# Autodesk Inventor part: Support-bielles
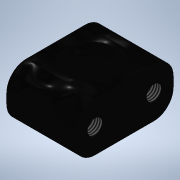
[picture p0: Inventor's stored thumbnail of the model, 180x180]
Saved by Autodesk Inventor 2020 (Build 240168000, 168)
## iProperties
Created: 2023-10
Part Number: Support-bielles
Material: Générique
Document SubType Name: Modeling
Designer: bruno
Density: 1 g/cm^3
Appearance: Noir
Author: bruno
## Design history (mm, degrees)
sketch "Esquisse1"
  geometry: L1 (4, 0)-(6, 0); L2 (10, -4)-(10, -16); L3 (6, -20)-(4, -20); L4 (0, -16)-(0, -4); A1 r 4 centre (6, -4) between (10, -4) and (6, 0); A2 r 4 centre (4, -4) between (4, 0) and (0, -4); A3 r 4 centre (4, -16) between (0, -16) and (4, -20); A4 r 4 centre (6, -16) between (6, -20) and (10, -16); 4 further points
  constraints: 8 end point, 8 point on circle, 8 point on line, 8 tangent, 4 centre point, 3 equal radius, 2 parallel, 1 horizontal, 1 perpendicular
  dimensions: "d0" = 10 distance of point (10, -20) point (0, -20); "d1" = 20 distance of point (10, 0) point (10, -20); "d2" = 4 radius of A1
extrude "Extrusion1" new body sketch "Esquisse1" distance "d3" = 14; taper "d4" = 0 deg
sketch "Esquisse2"
  geometry: L1 (0, 12)-(0, 0) reference; L2 (14, 12)-(14, 0) reference; L3 (0, 0)-(14, 12); C1 r 5 at (7, 6); 1 further point
  constraints: 2 end point, 1 centre point, 1 midpoint
  dimensions: "d5" = 10 diameter of C1
extrude "Extrusion2" cut sketch "Esquisse2" distance "d6" = 14; taper "d7" = 0 deg
sketch "Esquisse3"
  geometry: L1 (4, 0)-(16, 0) reference; L2 (20, 4)-(20, 6) reference; L3 (16, 10)-(4, 10) reference; L4 (0, 6)-(0, 4) reference; L5 (0, 5)-(20, 5); L6 (20, 4)-(20, 6) reference; C1 r 1.5 at (4, 5); C2 r 1.5 at (16, 5); A1 r 4 centre (4, 4) between (0, 4) and (4, 0) reference; A2 r 4 centre (16, 4) between (16, 0) and (20, 4) reference; A3 r 4 centre (16, 6) between (20, 6) and (16, 10) reference; A4 r 4 centre (4, 6) between (4, 10) and (0, 6) reference; 1 further point
  constraints: 2 centre point, 2 end point, 2 midpoint, 2 point on line
  dimensions: "d8" = 3 diameter of C1; "d9" = 4 distance from line of L4 C1.centre; "d10" = 3 diameter of C2; "d11" = 4 distance from line of L2 C2.centre
extrude "Extrusion3" cut sketch "Esquisse3" distance "d12" = 7; taper "d13" = 0 deg
feature "Filetage1" dims "d14" = 10, "d15" = 0
feature "Filetage2" dims "d16" = 10, "d17" = 0
node "Solide1"
node "Boucle projetée1"
